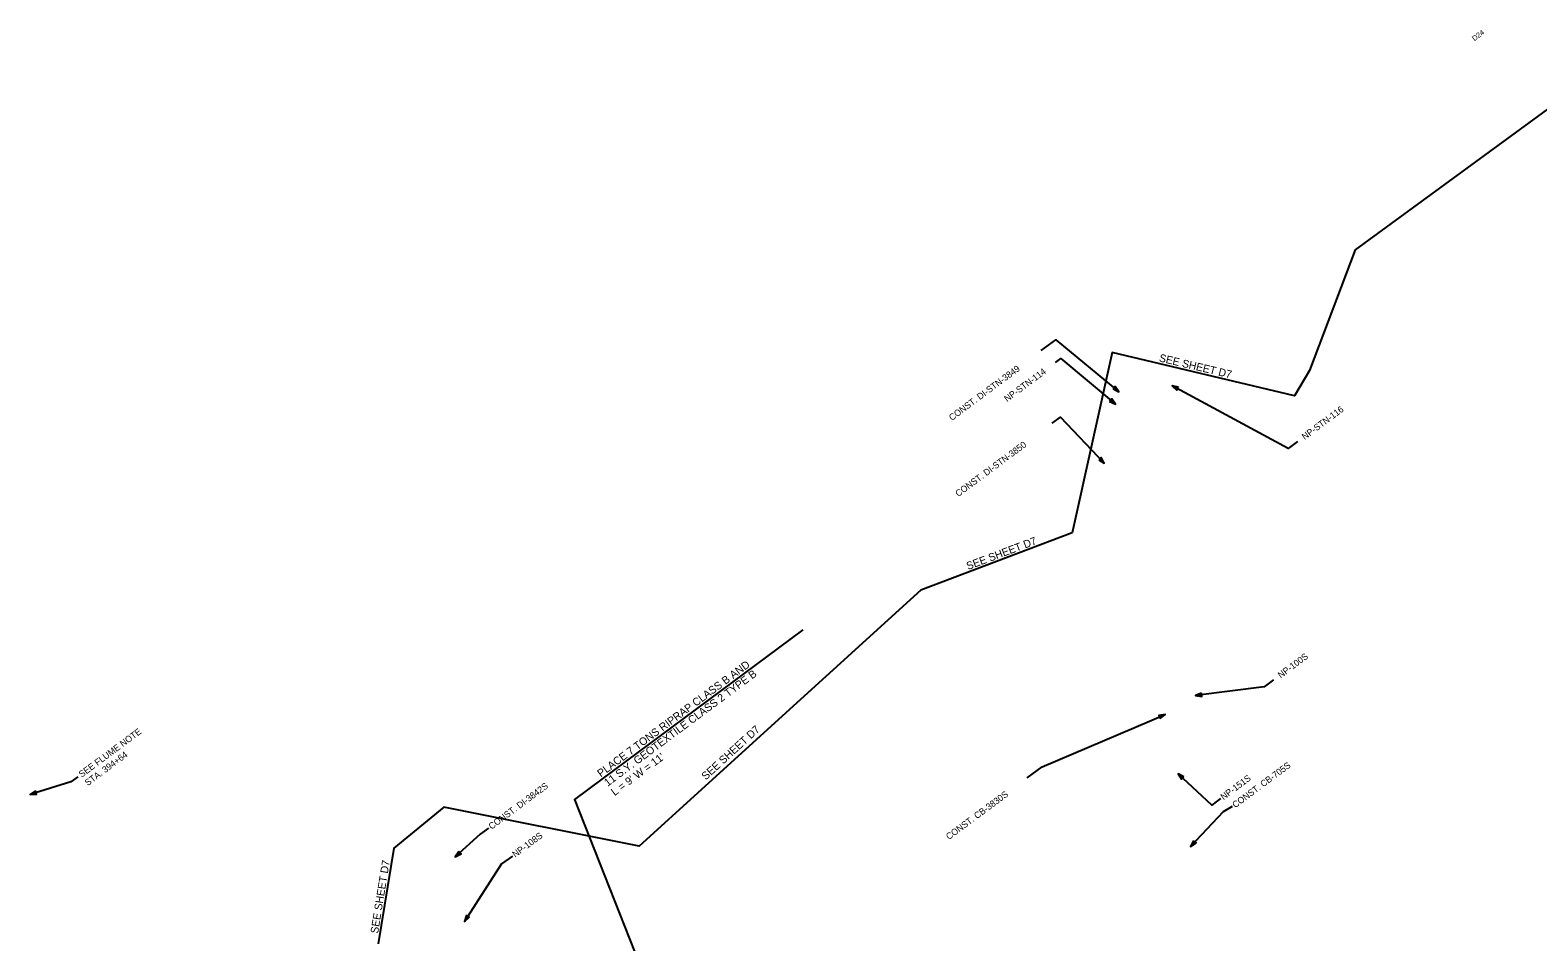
# Model space of a CAD drawing. Extents: x 1610466 to 1612467, y 1092226 to 1094137.
# Drawn here: x 1610565 to 1611735, y 1093429 to 1094137 of the extents above; entities that cross this region are included whole.
import ezdxf

# ---------------------------------------------------------------- set-up
doc = ezdxf.new("R2010")
doc.units = 0
for name, color, linetype in [('Plan_Clip', 7, 'Continuous'), ('RD_SHT_Bndy', 7, 'Continuous'), ('RD_SHT_MatchLine', 7, 'Continuous'), ('RD_TX_Drainage', 7, 'Continuous')]:
    doc.layers.add(name, color=color, linetype=linetype)

msp = doc.modelspace()

# ---------------------------------------------------------------- linework, layer by layer
at = {"layer": 'Plan_Clip'}
msp.add_lwpolyline([(1611745, 1094077.4), (1611593, 1093966.1), (1611557.4, 1093872.4), (1611545.9, 1093852.8), (1611404.5, 1093886.4), (1611373.3, 1093746.6), (1611255.8, 1093702.1), (1611182.1, 1093635), (1611037.4, 1093503.3), (1610885.8, 1093533.5), (1610846.9, 1093501.7), (1610834.8, 1093427.6)], dxfattribs=at)
at = {"layer": 'RD_TX_Drainage'}
msp.add_line((1611164.4, 1093671.3), (1611008.5, 1093555.4), dxfattribs=at)
for points in [[(1611349.4, 1093887.9), (1611360.7, 1093896.3), (1611409.6, 1093856)], [(1611360.4, 1093878.7), (1611364.5, 1093881.8), (1611407, 1093846.3)], [(1611548.2, 1093817.4), (1611541, 1093812), (1611451, 1093860.6)], [(1611357.9, 1093831.5), (1611364.3, 1093836.2), (1611398.3, 1093800.5)], [(1611529.7, 1093632.4), (1611522.4, 1093627), (1611469, 1093620.2)], [(1611338.4, 1093556.3), (1611350, 1093564.9), (1611445.6, 1093605.5)], [(1610601.7, 1093557.2), (1610596.3, 1093553.2), (1610564.8, 1093543.5)], [(1611008.5, 1093555.4), (1610987.3, 1093539.6), (1611033.7, 1093421.5), (1611218.3, 1093160.6)], [(1611488.5, 1093540.3), (1611481.7, 1093535.2), (1611455.5, 1093559.4)], [(1611497.6, 1093534.1), (1611490.6, 1093529.9), (1611465.2, 1093503.2)], [(1610920.5, 1093517.4), (1610913.9, 1093512.6), (1610894.7, 1093495)], [(1610939, 1093495.7), (1610930.6, 1093489.5), (1610901.8, 1093444.9)]]:
    msp.add_lwpolyline(points, dxfattribs=at)
for points in [[(1611405.1, 1093858.1), (1611409.6, 1093856), (1611406.7, 1093860.1)], [(1611455.9, 1093859.4), (1611451, 1093860.6), (1611454.7, 1093857.2)], [(1611402.4, 1093848.4), (1611407, 1093846.3), (1611404.1, 1093850.4)], [(1611394.1, 1093803.1), (1611398.3, 1093800.5), (1611395.9, 1093804.9)], [(1611473.6, 1093622.1), (1611469, 1093620.2), (1611474, 1093619.5)], [(1611441.6, 1093602.4), (1611445.6, 1093605.5), (1611440.6, 1093604.8)], [(1611459.9, 1093557.1), (1611455.5, 1093559.4), (1611458.2, 1093555.2)], [(1610569, 1093546.2), (1610564.8, 1093543.5), (1610569.8, 1093543.7)], [(1611467.6, 1093507.6), (1611465.2, 1093503.2), (1611469.5, 1093505.9)], [(1610897.4, 1093499.2), (1610894.7, 1093495), (1610899.2, 1093497.3)], [(1610903.3, 1093449.7), (1610901.8, 1093444.9), (1610905.5, 1093448.3)]]:
    msp.add_lwpolyline(points, close=True, dxfattribs=at)

# ---------------------------------------------------------------- texts
at = {"layer": 'RD_SHT_Bndy'}
msp.add_text('D24', height=4, rotation=36.6256, dxfattribs=at).set_placement((1611685.5, 1094127.9))
at = {"layer": 'RD_SHT_MatchLine'}
for rotation, p in [(346.6096, (1611440.4, 1093879.6)), (20.7167, (1611292.6, 1093717.6)), (42.4557, (1611089.1, 1093554.3)), (80.7664, (1610834.7, 1093435.2))]:
    msp.add_text('SEE SHEET D7', height=6, rotation=rotation, dxfattribs=at).set_placement(p)
at = {"layer": 'RD_TX_Drainage'}
for s, height, p in [('CONST. DI-STN-3849', 5, (1611280, 1093833.2)), ('NP-STN-114', 5, (1611322.9, 1093847.8)), ('NP-STN-116', 5, (1611553.8, 1093818.4)), ('CONST. DI-STN-3850', 5, (1611285, 1093774.2)), ('PLACE 7 TONS RIPRAP CLASS B AND', 6, (1611007.6, 1093556.6)), ('NP-100S', 5, (1611535.2, 1093633.4)), ('11 S.Y. GEOTEXTILE CLASS 2 TYPE B', 6, (1611012.9, 1093549.4)), ('SEE FLUME NOTE', 5, (1610604.8, 1093556.4)), ('STA. 394+64', 5, (1610609.5, 1093549.9)), ("L = 9' W = 11'", 6, (1611018.3, 1093542.1)), ('CONST. CB-705S', 5, (1611499.9, 1093532.7)), ('CONST. DI-3842S', 5, (1610922.8, 1093516)), ('NP-151S', 5, (1611490.8, 1093538.9)), ('CONST. CB-3830S', 5, (1611277.7, 1093508)), ('NP-108S', 5, (1610941.2, 1093494.3))]:
    msp.add_text(s, height=height, rotation=36.6256, dxfattribs=at).set_placement(p)

doc.saveas('drawing.dxf')
